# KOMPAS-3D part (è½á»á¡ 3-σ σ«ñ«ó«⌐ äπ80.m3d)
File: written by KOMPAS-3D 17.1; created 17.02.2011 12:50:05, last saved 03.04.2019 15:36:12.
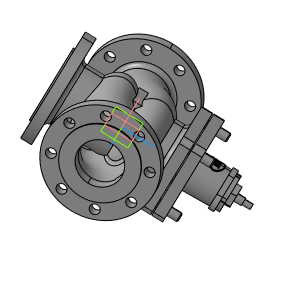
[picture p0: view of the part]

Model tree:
1. Плоскость XY
2. Плоскость ZX
3. Плоскость ZY
4. Ось X
5. Ось Y
6. Ось Z
7. Начало координат
8. Операция без истории:3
